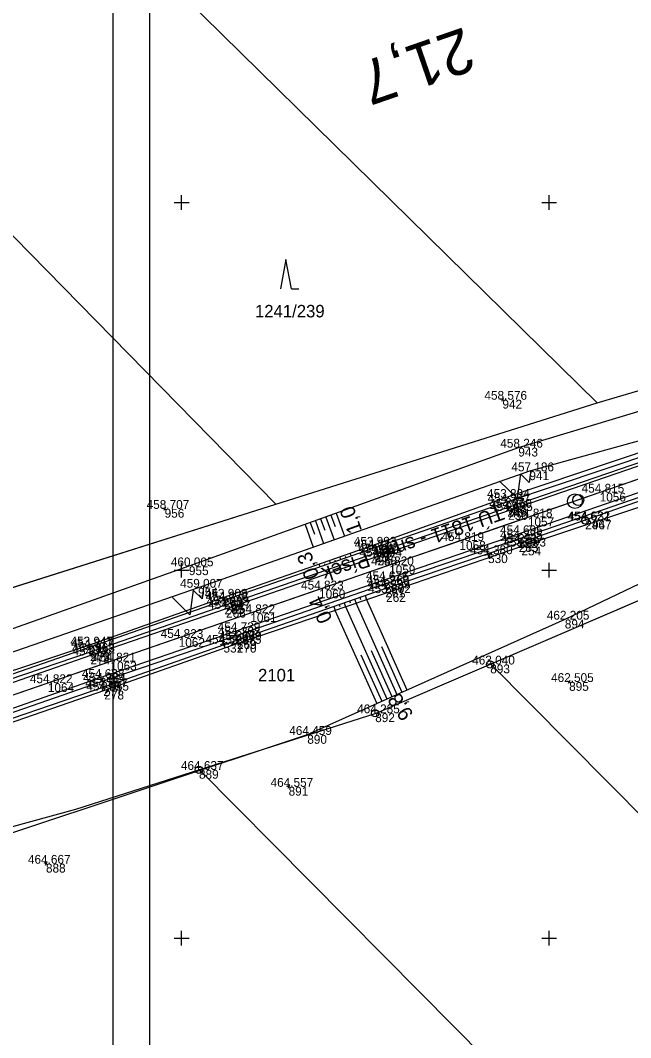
# Model space of a CAD drawing. Extents: x -776734 to -748832, y -1118122 to -976986.
# Drawn here: x -751372 to -751288.9, y -1114813.5 to -1114675.2 of the extents above; entities that cross this region are included whole.
import ezdxf

# ---------------------------------------------------------------- set-up
doc = ezdxf.new("R2010")
doc.units = 0
for name, color, linetype in [('KM_Hranice parcel', 7, 'Continuous'), ('KM_Parcelní čísla', 7, 'Continuous'), ('KM_Značky kultur', 7, 'Continuous'), ('Legenda 1 rámy + tabulka + severka', 7, 'Continuous'), ('Level 61 Křížky', 7, 'Continuous'), ('OSA', 7, 'Continuous'), ('SŽG Vrstva 1', 7, 'Continuous'), ('SŽG Vrstva 4', 7, 'Continuous'), ('SŽG Vrstva 48', 7, 'Continuous'), ('SŽG Vrstva 49', 7, 'Continuous'), ('SŽG Vrstva 50', 7, 'Continuous'), ('SŽG Vrstva 53', 7, 'Continuous'), ('SŽG Vrstva 60', 7, 'Continuous'), ('SŽG Vrstva 61', 7, 'Continuous'), ('SŽG Vrstva 7', 7, 'Continuous')]:
    doc.layers.add(name, color=color, linetype=linetype)

msp = doc.modelspace()

# ---------------------------------------------------------------- linework, layer by layer
at = {"layer": 'KM_Hranice parcel'}
for p, q in [((-751293.44, -1114727.24), (-751406.13, -1114616.64)), ((-751439.38, -1114637.08), (-751337.18, -1114740.99)), ((-751337.18, -1114740.99), (-751293.44, -1114727.24)), ((-751377.2, -1114753.63), (-751337.18, -1114740.99)), ((-751268.46, -1114745.82), (-751307.93, -1114762.77))]:
    msp.add_line(p, q, dxfattribs=at)
for points in [[(-751293.44, -1114727.24), (-751276.39, -1114722.19), (-751236.9, -1114707.02)], [(-751307.93, -1114762.77), (-751323.57, -1114769.49), (-751347.57, -1114777.14)], [(-751307.93, -1114762.77), (-751286.55, -1114784.31), (-751238.76, -1114832.46), (-751161.13, -1114910.68), (-751116.44, -1114955.71)], [(-751347.57, -1114777.14), (-751364.44, -1114782.53), (-751398.43, -1114791.82)], [(-751126.76, -1114999.86), (-751195.24, -1114930.79), (-751259.42, -1114866.05), (-751317.55, -1114807.42), (-751347.57, -1114777.14)]]:
    msp.add_lwpolyline(points, dxfattribs=at)
at = {"layer": 'KM_Značky kultur'}
for p, q in [((-751335.8194, -1114707.7438), (-751336.5694, -1114711.7438)), ((-751335.0694, -1114711.7438), (-751335.8194, -1114707.7438)), ((-751335.0694, -1114711.7438), (-751334.0734, -1114711.7438))]:
    msp.add_line(p, q, dxfattribs=at)
at = {"layer": 'Legenda 1 rámy + tabulka + severka'}
for p, q in [((-751354.3274, -1114876.3246), (-751354.3274, -1114466.3246)), ((-751359.3274, -1114881.3246), (-751359.3274, -1114671.3246))]:
    msp.add_line(p, q, dxfattribs=at)
at = {"layer": 'Level 61 Křížky'}
for p, q in [((-751350, -1114700), (-751350, -1114699)), ((-751300, -1114700), (-751300, -1114699)), ((-751351, -1114700), (-751349, -1114700)), ((-751350, -1114701), (-751350, -1114700)), ((-751301, -1114700), (-751299, -1114700)), ((-751300, -1114701), (-751300, -1114700)), ((-751350, -1114750), (-751350, -1114749)), ((-751300, -1114750), (-751300, -1114749)), ((-751351, -1114750), (-751349, -1114750)), ((-751350, -1114751), (-751350, -1114750)), ((-751301, -1114750), (-751299, -1114750)), ((-751300, -1114751), (-751300, -1114750)), ((-751350, -1114800), (-751350, -1114799)), ((-751300, -1114800), (-751300, -1114799)), ((-751351, -1114800), (-751349, -1114800)), ((-751350, -1114801), (-751350, -1114800)), ((-751301, -1114800), (-751299, -1114800)), ((-751300, -1114801), (-751300, -1114800))]:
    msp.add_line(p, q, dxfattribs=at)
at = {"layer": 'OSA'}
for p, q in [((-751221.2446, -1114714.6435), (-751305.6868, -1114743.777)), ((-751305.6868, -1114743.777), (-751648.6661, -1114862.1099))]:
    msp.add_line(p, q, dxfattribs=at)
msp.add_circle((-751296.4756, -1114740.599), 1, dxfattribs=at)
at = {"layer": 'SŽG Vrstva 1'}
msp.add_lwpolyline([(-751216.509, -1114713.014), (-751226.434, -1114716.437), (-751236.324, -1114719.849), (-751245.849, -1114723.137), (-751255.285, -1114726.393), (-751264.701, -1114729.644), (-751273.956, -1114732.837), (-751283.458, -1114736.112), (-751293.108, -1114739.442), (-751302.881, -1114742.811), (-751312.192, -1114746.024), (-751321.757, -1114749.321), (-751331.295, -1114752.611), (-751340.65, -1114755.838), (-751350.401, -1114759.203), (-751359.686, -1114762.406), (-751368.209, -1114765.344), (-751379.178, -1114769.127)], dxfattribs=at)
at = {"layer": 'SŽG Vrstva 4'}
for points in [[(-751187.894, -1114700.58), (-751206.028, -1114707.041), (-751231.235, -1114715.596), (-751249.544, -1114721.971), (-751267.723, -1114728.471), (-751285.298, -1114734.541), (-751305.686, -1114741.509), (-751323.628, -1114747.668), (-751344.164, -1114754.785), (-751362.443, -1114761.123), (-751382.646, -1114767.996), (-751419.827, -1114780.907), (-751439.841, -1114787.752), (-751459.648, -1114794.565), (-751479.262, -1114801.395), (-751499.563, -1114808.301), (-751517.656, -1114814.613), (-751524.467, -1114817.135), (-751524.911, -1114817.646)], [(-751186.455, -1114705.269), (-751204.57, -1114711.262), (-751229.26, -1114719.967), (-751248.511, -1114726.389), (-751266.031, -1114732.591), (-751283.828, -1114738.73), (-751304.211, -1114745.766), (-751322.374, -1114751.898), (-751342.612, -1114758.897), (-751360.965, -1114765.168), (-751381.114, -1114772.121), (-751418.537, -1114784.997), (-751438.613, -1114791.912), (-751458.172, -1114798.656), (-751477.814, -1114805.419), (-751497.901, -1114812.476), (-751516.513, -1114818.688), (-751522.385, -1114820.606), (-751523.195, -1114820.521)], [(-751205.795, -1114707.603), (-751230.97, -1114716.264), (-751249.417, -1114722.675), (-751267.451, -1114728.869), (-751285.106, -1114734.872), (-751305.56, -1114741.936), (-751323.346, -1114748.135), (-751343.956, -1114755.234), (-751362.406, -1114761.583), (-751382.455, -1114768.543), (-751419.68, -1114781.407), (-751439.787, -1114788.305), (-751459.372, -1114795.057), (-751479.147, -1114801.881), (-751499.337, -1114808.873), (-751517.572, -1114815.159), (-751524.911, -1114817.646)], [(-751204.677, -1114710.75), (-751229.564, -1114719.281), (-751248.527, -1114725.936), (-751266.247, -1114732.037), (-751284.071, -1114738.15), (-751304.213, -1114745.084), (-751322.473, -1114751.338), (-751342.638, -1114758.269), (-751361.135, -1114764.639), (-751381.339, -1114771.707), (-751418.714, -1114784.623), (-751438.728, -1114791.466), (-751458.255, -1114798.22), (-751477.955, -1114804.997), (-751498.184, -1114811.907), (-751516.629, -1114818.238), (-751523.195, -1114820.521)]]:
    msp.add_lwpolyline(points, dxfattribs=at)
at = {"layer": 'SŽG Vrstva 48'}
for p, q in [((-751328.971, -1114742.245), (-751327.844, -1114745.377)), ((-751332.5, -1114743.515), (-751331.941, -1114745.067)), ((-751331.794, -1114743.261), (-751330.675, -1114746.371)), ((-751331.089, -1114743.007), (-751330.528, -1114744.565)), ((-751330.383, -1114742.753), (-751329.26, -1114745.874)), ((-751329.677, -1114742.499), (-751329.115, -1114744.063)), ((-751333.206, -1114743.769), (-751332.09, -1114746.868)), ((-751326.9183, -1114748.0536), (-751327.0501, -1114747.6764)), ((-751331.1667, -1114749.5373), (-751331.2985, -1114749.16)), ((-751330.4586, -1114749.29), (-751330.5245, -1114749.1014)), ((-751329.7506, -1114749.0427), (-751329.8823, -1114748.6655)), ((-751329.0425, -1114748.7954), (-751329.1084, -1114748.6068)), ((-751328.3345, -1114748.5481), (-751328.4662, -1114748.1709)), ((-751327.6264, -1114748.3009), (-751327.6923, -1114748.1123)), ((-751325.044, -1114753.4192), (-751324.8391, -1114754.0059)), ((-751328.5843, -1114754.6557), (-751328.4872, -1114754.9336)), ((-751327.8762, -1114754.4084), (-751327.68, -1114754.9704)), ((-751327.1682, -1114754.1611), (-751327.069, -1114754.4452)), ((-751326.4601, -1114753.9138), (-751326.2595, -1114754.4881)), ((-751320.6716, -1114766.9145), (-751326.2333, -1114754.4792)), ((-751325.7521, -1114753.6665), (-751325.6507, -1114753.9568)), ((-751319.3023, -1114766.3021), (-751324.8067, -1114753.9948)), ((-751329.2924, -1114754.903), (-751329.1004, -1114755.4526)), ((-751323.4102, -1114768.1394), (-751329.0864, -1114755.4479)), ((-751322.0409, -1114767.5269), (-751327.6598, -1114754.9635)), ((-751322.7255, -1114767.8332), (-751325.5493, -1114761.5194)), ((-751321.3562, -1114767.2207), (-751324.1514, -1114760.9711)), ((-751319.9869, -1114766.6083), (-751322.7535, -1114760.4227))]:
    msp.add_line(p, q, dxfattribs=at)
at = {"layer": 'SŽG Vrstva 49'}
for p, q in [((-751306.1203, -1114726.9205), (-751306.5697, -1114726.7015)), ((-751306.2355, -1114726.5863), (-751306.4545, -1114727.0357)), ((-751352.0912, -1114741.7575), (-751352.5408, -1114741.5385)), ((-751352.2065, -1114741.4232), (-751352.4255, -1114741.8728)), ((-751297.0423, -1114765.2965), (-751297.4917, -1114765.0775)), ((-751297.1575, -1114764.9623), (-751297.3765, -1114765.4117)), ((-751335.2193, -1114779.5485), (-751335.6687, -1114779.3295)), ((-751335.3345, -1114779.2143), (-751335.5535, -1114779.6637)), ((-751368.2442, -1114790.0055), (-751368.6938, -1114789.7865)), ((-751368.3595, -1114789.6712), (-751368.5785, -1114790.1208))]:
    msp.add_line(p, q, dxfattribs=at)
for points in [[(-751234.949, -1114713.279), (-751245.481, -1114717.135), (-751281.469, -1114726.527), (-751304.183, -1114733.326), (-751349.012, -1114749.456), (-751398.203, -1114766.871), (-751445.795, -1114779.905), (-751491.917, -1114801.089), (-751522.469, -1114813.154), (-751523.879, -1114811.232), (-751530.057, -1114804.525)], [(-751231.525, -1114714.481), (-751249.638, -1114721.458), (-751267.891, -1114727.816), (-751285.514, -1114733.952), (-751305.908, -1114740.796), (-751324.002, -1114747.035), (-751344.265, -1114754.112), (-751362.586, -1114760.516), (-751382.595, -1114767.438), (-751402.409, -1114774.045), (-751420.234, -1114780.2), (-751439.893, -1114787.152), (-751459.921, -1114794.045), (-751479.467, -1114800.491), (-751499.785, -1114807.5), (-751517.869, -1114814.102), (-751523.111, -1114815.97), (-751524.209, -1114815.639), (-751526.184, -1114811.436)], [(-751244.9, -1114718.575), (-751249.937, -1114720.628), (-751268.48, -1114726.929), (-751276.661, -1114729.623), (-751285.758, -1114733.326), (-751305.984, -1114740.165), (-751324.128, -1114746.656), (-751344.388, -1114753.731), (-751362.684, -1114760.234), (-751382.771, -1114766.903), (-751402.562, -1114773.563), (-751420.499, -1114779.462), (-751440.12, -1114786.635), (-751460.286, -1114793.369), (-751479.705, -1114799.993), (-751499.94, -1114807.004), (-751518.245, -1114813.43), (-751522.739, -1114814.822), (-751523.674, -1114814.114), (-751524.925, -1114811.322)], [(-751523.899, -1114821.949), (-751516.26, -1114819.366), (-751497.387, -1114813.062), (-751477.616, -1114806.13), (-751458.015, -1114799.124), (-751438.432, -1114792.474), (-751418.478, -1114785.506), (-751400.555, -1114779.532), (-751380.096, -1114772.486), (-751360.669, -1114765.898), (-751342.469, -1114759.505), (-751322.286, -1114752.456), (-751304.11, -1114746.299), (-751283.779, -1114739.207), (-751265.74, -1114733.22), (-751248.287, -1114727.037), (-751240.07, -1114724.297)], [(-751240.236, -1114725.654), (-751248.02, -1114728.046), (-751265.488, -1114734.037), (-751283.474, -1114739.989), (-751303.76, -1114746.769), (-751322.174, -1114753.101), (-751342.488, -1114759.998), (-751360.52, -1114766.361), (-751379.963, -1114773.044), (-751400.343, -1114780.093), (-751418.294, -1114786.259), (-751438.171, -1114793.174), (-751457.682, -1114799.957), (-751477.222, -1114807.057), (-751497.375, -1114813.972), (-751516.217, -1114820.454), (-751522.915, -1114822.926), (-751523.899, -1114821.949)], [(-751204.754, -1114724.609), (-751227.195, -1114725.505), (-751238.195, -1114726.494), (-751253.205, -1114735.378), (-751297.853, -1114756.709), (-751332.903, -1114772.385), (-751375.498, -1114786.511), (-751400.696, -1114793.558), (-751443.206, -1114803.356), (-751482.539, -1114812.284)], [(-751276.661, -1114729.623), (-751280.138, -1114730.299), (-751302.673, -1114736.54), (-751347.758, -1114752.369), (-751397.367, -1114769.54), (-751443.606, -1114786.702), (-751459.316, -1114792.112), (-751460.286, -1114793.369)]]:
    msp.add_lwpolyline(points, dxfattribs=at)
at = {"layer": 'SŽG Vrstva 50'}
for points in [[(-751302.469, -1114736.3918), (-751302.6888, -1114738.0544), (-751303.887, -1114736.881), (-751304.3266, -1114740.2062), (-751306.723, -1114737.8594)], [(-751347.007, -1114752.233), (-751347.227, -1114753.8955), (-751348.425, -1114752.722), (-751348.865, -1114756.0471), (-751351.2611, -1114753.7)]]:
    msp.add_lwpolyline(points, dxfattribs=at)
at = {"layer": 'SŽG Vrstva 53'}
for p, q in [((-751307.9567, -1114762.7917), (-751308.0513, -1114762.8243)), ((-751323.6127, -1114769.4227), (-751323.7073, -1114769.4553)), ((-751347.5967, -1114777.1207), (-751347.6913, -1114777.1533))]:
    msp.add_line(p, q, dxfattribs=at)
for points in [[(-751615.07, -1114840.52), (-751596.62, -1114835), (-751572.02, -1114827.5), (-751551.31, -1114808.23), (-751526.51, -1114811.39), (-751501.68, -1114801.88), (-751460.63, -1114785.23), (-751418.82, -1114768.72), (-751390.21, -1114757.9), (-751377.2, -1114753.63), (-751337.18, -1114740.99), (-751293.44, -1114727.24), (-751276.39, -1114722.19), (-751236.9, -1114707.02), (-751193.03, -1114664.28), (-751178.42, -1114675.26), (-751174.34, -1114678.03), (-751162.9, -1114674.22), (-751118.39, -1114659.47), (-751098.21, -1114652.66), (-751091.59, -1114651.24)], [(-751047.63, -1114693.52), (-751057.9, -1114691.02), (-751081.52, -1114685.27), (-751134.08, -1114703.51), (-751142.83, -1114706.54), (-751153.31, -1114710.17), (-751137.57, -1114746.06), (-751139.06, -1114746.27), (-751138.42, -1114748.17), (-751151.05, -1114751.02), (-751162.24, -1114725.26), (-751172.58, -1114730.25), (-751213.65, -1114726.85), (-751218.67, -1114726.44), (-751268.46, -1114745.82), (-751307.93, -1114762.77), (-751323.57, -1114769.49), (-751347.57, -1114777.14), (-751364.44, -1114782.53), (-751398.43, -1114791.82)]]:
    msp.add_lwpolyline(points, dxfattribs=at)
for centre in [(-751308.004, -1114762.808), (-751323.66, -1114769.439), (-751347.644, -1114777.137)]:
    msp.add_circle(centre, 0.4993, dxfattribs=at)
at = {"layer": 'SŽG Vrstva 60'}
for p, q in [((-751306.345, -1114726.811), (-751306.345, -1114726.811)), ((-751304.183, -1114733.326), (-751304.183, -1114733.326)), ((-751302.673, -1114736.54), (-751302.673, -1114736.54)), ((-751293.108, -1114739.442), (-751293.108, -1114739.442)), ((-751305.984, -1114740.165), (-751305.984, -1114740.165)), ((-751305.908, -1114740.796), (-751305.908, -1114740.796)), ((-751352.316, -1114741.648), (-751352.316, -1114741.648)), ((-751305.686, -1114741.509), (-751305.686, -1114741.509)), ((-751305.56, -1114741.936), (-751305.56, -1114741.936)), ((-751302.881, -1114742.811), (-751302.881, -1114742.811)), ((-751295.075, -1114743.222), (-751295.075, -1114743.222)), ((-751295.054, -1114743.207), (-751295.054, -1114743.207)), ((-751304.213, -1114745.084), (-751304.213, -1114745.084)), ((-751312.192, -1114746.024), (-751312.192, -1114746.024)), ((-751304.211, -1114745.766), (-751304.211, -1114745.766)), ((-751304.11, -1114746.299), (-751304.11, -1114746.299)), ((-751324.128, -1114746.656), (-751324.128, -1114746.656)), ((-751324.002, -1114747.035), (-751324.002, -1114747.035)), ((-751323.628, -1114747.668), (-751323.628, -1114747.668)), ((-751308.299, -1114747.817), (-751308.299, -1114747.817)), ((-751303.76, -1114746.769), (-751303.76, -1114746.769)), ((-751323.346, -1114748.135), (-751323.346, -1114748.135)), ((-751349.012, -1114749.456), (-751349.012, -1114749.456)), ((-751321.757, -1114749.321), (-751321.757, -1114749.321)), ((-751322.473, -1114751.338), (-751322.473, -1114751.338)), ((-751322.374, -1114751.898), (-751322.374, -1114751.898)), ((-751347.758, -1114752.369), (-751347.758, -1114752.369)), ((-751331.295, -1114752.611), (-751331.295, -1114752.611)), ((-751322.286, -1114752.456), (-751322.286, -1114752.456)), ((-751322.174, -1114753.101), (-751322.174, -1114753.101)), ((-751344.388, -1114753.731), (-751344.388, -1114753.731)), ((-751344.265, -1114754.112), (-751344.265, -1114754.112)), ((-751344.164, -1114754.785), (-751344.164, -1114754.785)), ((-751343.956, -1114755.234), (-751343.956, -1114755.234)), ((-751340.65, -1114755.838), (-751340.65, -1114755.838)), ((-751297.853, -1114756.709), (-751297.853, -1114756.709)), ((-751342.638, -1114758.269), (-751342.638, -1114758.269)), ((-751342.612, -1114758.897), (-751342.612, -1114758.897)), ((-751362.684, -1114760.234), (-751362.684, -1114760.234)), ((-751350.401, -1114759.203), (-751350.401, -1114759.203)), ((-751344.309, -1114759.981), (-751344.309, -1114759.981)), ((-751342.488, -1114759.998), (-751342.488, -1114759.998)), ((-751342.469, -1114759.505), (-751342.469, -1114759.505)), ((-751362.586, -1114760.516), (-751362.586, -1114760.516)), ((-751362.443, -1114761.123), (-751362.443, -1114761.123)), ((-751362.406, -1114761.583), (-751362.406, -1114761.583)), ((-751359.686, -1114762.406), (-751359.686, -1114762.406)), ((-751308.004, -1114762.808), (-751308.004, -1114762.808)), ((-751368.209, -1114765.344), (-751368.209, -1114765.344)), ((-751361.135, -1114764.639), (-751361.135, -1114764.639)), ((-751360.965, -1114765.168), (-751360.965, -1114765.168)), ((-751297.267, -1114765.187), (-751297.267, -1114765.187)), ((-751360.669, -1114765.898), (-751360.669, -1114765.898)), ((-751360.52, -1114766.361), (-751360.52, -1114766.361)), ((-751323.66, -1114769.439), (-751323.66, -1114769.439)), ((-751332.903, -1114772.385), (-751332.903, -1114772.385)), ((-751347.644, -1114777.137), (-751347.644, -1114777.137)), ((-751335.444, -1114779.439), (-751335.444, -1114779.439)), ((-751368.469, -1114789.896), (-751368.469, -1114789.896))]:
    msp.add_line(p, q, dxfattribs=at)
at = {"layer": 'SŽG Vrstva 7'}
for p, q in [((-751295.0277, -1114743.2057), (-751295.1223, -1114743.2383)), ((-751295.0067, -1114743.1907), (-751295.1013, -1114743.2233)), ((-751307.8263, -1114747.6539), (-751308.7717, -1114747.9801)), ((-751308.1359, -1114748.2897), (-751308.4621, -1114747.3443)), ((-751343.8364, -1114759.8179), (-751344.7816, -1114760.1441)), ((-751344.1459, -1114760.4536), (-751344.4721, -1114759.5084))]:
    msp.add_line(p, q, dxfattribs=at)
for centre, radius in [((-751296.0307, -1114740.4495), 0.75), ((-751295.075, -1114743.222), 0.5), ((-751295.054, -1114743.207), 0.5)]:
    msp.add_circle(centre, radius, dxfattribs=at)

# ---------------------------------------------------------------- texts
at = {"layer": 'KM_Parcelní čísla'}
for s, p in [('1241/239', (-751340.0214, -1114715.6142)), ('2101', (-751339.6054, -1114765.1007))]:
    msp.add_text(s, height=1.7, dxfattribs=at).set_placement(p)
at = {"layer": 'OSA'}
for s, height, rotation, p in [('21,7', 6, 199.034988, (-751311.5347, -1114676.1011)), ('TÚ 1811 - směr Písek', 2, 199.282328, (-751306.5748, -1114741.1336))]:
    msp.add_text(s, height=height, rotation=rotation, dxfattribs=at).set_placement(p)
at = {"layer": 'SŽG Vrstva 48'}
for s, rotation, p in [('1,0', 109.789326, (-751325.418, -1114744.573)), ('0,3', 109.249726, (-751331.2519, -1114750.8235)), ('0,4', 114.251976, (-751329.4361, -1114756.6495)), ('9,8', 123.753354, (-751318.3724, -1114769.5634))]:
    msp.add_text(s, height=2, rotation=rotation, dxfattribs=at).set_placement(p)
at = {"layer": 'SŽG Vrstva 60'}
for s, p in [('942', (-751306.345, -1114728.011)), ('943', (-751304.183, -1114734.526)), ('941', (-751302.673, -1114737.74)), ('1056', (-751293.108, -1114740.642)), ('247', (-751305.984, -1114741.365)), ('248', (-751305.908, -1114741.996)), ('956', (-751352.316, -1114742.848)), ('249', (-751305.686, -1114742.709)), ('250', (-751305.56, -1114743.136)), ('1057', (-751302.881, -1114744.011)), ('246', (-751295.075, -1114744.422)), ('2947', (-751295.054, -1114744.407)), ('251', (-751304.213, -1114746.284)), ('1058', (-751312.192, -1114747.224)), ('252', (-751304.211, -1114746.966)), ('253', (-751304.11, -1114747.499)), ('255', (-751324.128, -1114747.856)), ('256', (-751324.002, -1114748.235)), ('257', (-751323.628, -1114748.868)), ('530', (-751308.299, -1114749.017)), ('254', (-751303.76, -1114747.969)), ('258', (-751323.346, -1114749.335)), ('955', (-751349.012, -1114750.656)), ('1059', (-751321.757, -1114750.521)), ('259', (-751322.473, -1114752.538)), ('260', (-751322.374, -1114753.098)), ('954', (-751347.758, -1114753.569)), ('1060', (-751331.295, -1114753.811)), ('261', (-751322.286, -1114753.656)), ('262', (-751322.174, -1114754.301)), ('263', (-751344.388, -1114754.931)), ('264', (-751344.265, -1114755.312)), ('265', (-751344.164, -1114755.985)), ('266', (-751343.956, -1114756.434)), ('1061', (-751340.65, -1114757.038)), ('894', (-751297.853, -1114757.909)), ('267', (-751342.638, -1114759.469)), ('268', (-751342.612, -1114760.097)), ('271', (-751362.684, -1114761.434)), ('1062', (-751350.401, -1114760.403)), ('531', (-751344.309, -1114761.181)), ('270', (-751342.488, -1114761.198)), ('269', (-751342.469, -1114760.705)), ('272', (-751362.586, -1114761.716)), ('273', (-751362.443, -1114762.323)), ('274', (-751362.406, -1114762.783)), ('1063', (-751359.686, -1114763.606)), ('893', (-751308.004, -1114764.008)), ('1064', (-751368.209, -1114766.544)), ('275', (-751361.135, -1114765.839)), ('276', (-751360.965, -1114766.368)), ('895', (-751297.267, -1114766.387)), ('277', (-751360.669, -1114767.098)), ('278', (-751360.52, -1114767.561)), ('892', (-751323.66, -1114770.639)), ('890', (-751332.903, -1114773.585)), ('889', (-751347.644, -1114778.337)), ('891', (-751335.444, -1114780.639)), ('888', (-751368.469, -1114791.096))]:
    msp.add_text(s, height=1.2, dxfattribs=at).set_placement(p)
at = {"layer": 'SŽG Vrstva 61'}
for s, p in [('458.576', (-751308.7969, -1114726.811)), ('458.246', (-751306.6349, -1114733.326)), ('457.186', (-751305.1249, -1114736.54)), ('453.894', (-751308.435, -1114740.165)), ('454.247', (-751308.3599, -1114740.796)), ('454.815', (-751295.5641, -1114739.442)), ('458.707', (-751354.7679, -1114741.648)), ('454.360', (-751308.137, -1114741.509)), ('454.695', (-751308.0161, -1114741.936)), ('454.818', (-751305.3347, -1114742.811)), ('454.622', (-751297.5022, -1114743.207)), ('454.631', (-751297.4324, -1114743.222)), ('454.819', (-751314.6457, -1114746.024)), ('454.695', (-751306.6691, -1114745.084)), ('454.235', (-751306.6671, -1114745.766)), ('454.237', (-751306.5619, -1114746.299)), ('453.993', (-751326.5799, -1114746.656)), ('454.313', (-751326.4539, -1114747.035)), ('454.361', (-751325.9854, -1114747.668)), ('453.893', (-751306.2119, -1114746.769)), ('454.694', (-751325.797, -1114748.135)), ('454.380', (-751310.75, -1114747.817)), ('460.005', (-751351.4681, -1114749.456)), ('454.820', (-751324.208, -1114749.321)), ('454.676', (-751324.9249, -1114751.338)), ('459.007', (-751350.2099, -1114752.369)), ('454.823', (-751333.7469, -1114752.611)), ('454.260', (-751324.825, -1114751.898)), ('454.239', (-751324.7397, -1114752.456)), ('453.872', (-751324.6222, -1114753.101)), ('453.908', (-751346.8417, -1114753.731)), ('454.278', (-751346.7187, -1114754.112)), ('454.303', (-751346.6159, -1114754.785)), ('454.627', (-751346.4079, -1114755.234)), ('454.822', (-751343.0982, -1114755.838)), ('462.205', (-751300.3091, -1114756.709)), ('454.739', (-751345.0917, -1114758.269)), ('454.823', (-751352.8529, -1114759.203)), ('454.523', (-751346.7609, -1114759.981)), ('454.303', (-751345.0639, -1114758.897)), ('453.975', (-751344.9441, -1114759.998)), ('454.269', (-751344.9227, -1114759.505)), ('453.947', (-751365.1359, -1114760.234)), ('454.317', (-751365.0379, -1114760.516)), ('454.363', (-751364.8949, -1114761.123)), ('454.724', (-751364.857, -1114761.583)), ('454.821', (-751362.0434, -1114762.406)), ('463.040', (-751310.455, -1114762.808)), ('454.822', (-751370.6572, -1114765.344)), ('454.688', (-751363.5887, -1114764.639)), ('454.284', (-751363.416, -1114765.168)), ('462.505', (-751299.7231, -1114765.187)), ('454.257', (-751363.1209, -1114765.898)), ('454.055', (-751362.9761, -1114766.361)), ('464.285', (-751326.1161, -1114769.439)), ('464.459', (-751335.3567, -1114772.385)), ('464.637', (-751350.0959, -1114777.137)), ('464.557', (-751337.8959, -1114779.439)), ('464.667', (-751370.9209, -1114789.896))]:
    msp.add_text(s, height=1.2, dxfattribs=at).set_placement(p)

doc.saveas('drawing.dxf')
